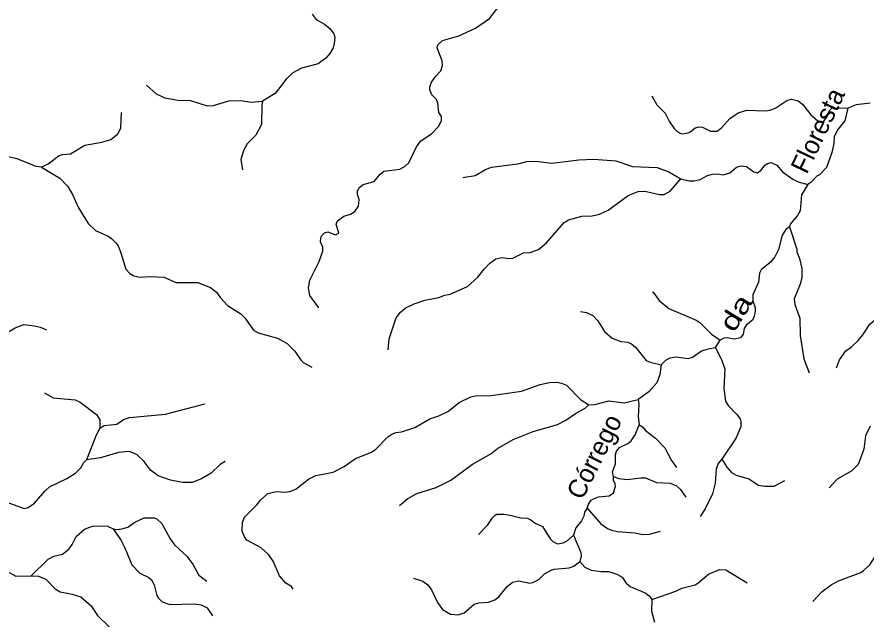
# Model space of a CAD drawing. Extents: x 577 to 602.9, y 7483.8 to 7511.6.
# Drawn here: x 589.273 to 592.922, y 7495.552 to 7498.138 of the extents above; entities that cross this region are included whole.
import ezdxf
from ezdxf.enums import TextEntityAlignment as Align

# ---------------------------------------------------------------- set-up
doc = ezdxf.new("R2010")
doc.units = 0
doc.header["$LTSCALE"] = 0.032
doc.layers.add('61', color=7, linetype='Continuous')
doc.layers.add('7', color=7, linetype='Continuous', lineweight=25)

msp = doc.modelspace()

# ---------------------------------------------------------------- linework, layer by layer
at = {"layer": '7'}
for points in [[(590.5706, 7496.8892), (590.5325, 7496.942), (590.5267, 7496.9755), (590.5325, 7497.0074), (590.5725, 7497.0883), (590.5872, 7497.1324), (590.5872, 7497.1488), (590.5782, 7497.1717), (590.579, 7497.1913), (590.5831, 7497.1995), (590.5954, 7497.2109), (590.6093, 7497.2158), (590.6428, 7497.2019), (590.6567, 7497.2101), (590.6453, 7497.2477), (590.651, 7497.2632), (590.678, 7497.282), (590.7066, 7497.2918), (590.7245, 7497.3033), (590.7409, 7497.3253), (590.7433, 7497.3548), (590.736, 7497.3768), (590.736, 7497.3907), (590.7442, 7497.4063), (590.7605, 7497.4193), (590.8079, 7497.4316), (590.8341, 7497.4635), (590.8496, 7497.4758), (590.9183, 7497.4847), (590.942, 7497.4978), (590.9575, 7497.5117), (590.9902, 7497.5804), (591.009, 7497.6057), (591.0548, 7497.636), (591.085, 7497.6678), (591.0973, 7497.6915), (591.0973, 7497.7112), (591.0858, 7497.7275), (591.0826, 7497.7676), (591.0768, 7497.7831), (591.0556, 7497.8035), (591.0474, 7497.8256), (591.0474, 7497.8387), (591.0548, 7497.8583), (591.0728, 7497.8845), (591.0948, 7497.9073), (591.1022, 7497.9294), (591.1006, 7497.9498), (591.0793, 7498.0054), (591.0826, 7498.0185), (591.1014, 7498.0373), (591.1717, 7498.0569), (591.2436, 7498.0896), (591.3041, 7498.1321), (591.3736, 7498.2229)], [(590.5414, 7498.1509), (590.5594, 7498.1272), (590.5946, 7498.1076), (590.6199, 7498.0872), (590.6346, 7498.0659), (590.6387, 7498.0512), (590.6371, 7498.025), (590.6314, 7498.0054), (590.6175, 7497.9809), (590.6011, 7497.9613), (590.5676, 7497.9376), (590.4965, 7497.918), (590.4589, 7497.8983), (590.4303, 7497.8714), (590.3829, 7497.8093), (590.3281, 7497.7766)], [(589.8297, 7497.8447), (589.8712, 7497.8076), (589.9088, 7497.7913), (589.9652, 7497.7815), (590.0183, 7497.7798), (590.0902, 7497.7561), (590.118, 7497.7578), (590.1842, 7497.7774), (590.2349, 7497.779), (590.2799, 7497.7725), (590.3281, 7497.7766)], [(592.0011, 7497.7998), (592.0234, 7497.7602), (592.0594, 7497.7251), (592.0757, 7497.6907), (592.097, 7497.6588), (592.1109, 7497.6458), (592.1297, 7497.6368), (592.1583, 7497.6409), (592.1697, 7497.6458), (592.1885, 7497.6621), (592.2041, 7497.6662), (592.2196, 7497.6654), (592.2531, 7497.6474), (592.2825, 7497.6474), (592.3013, 7497.6621), (592.3365, 7497.7022), (592.3724, 7497.7267), (592.41, 7497.7381), (592.4877, 7497.7357), (592.5098, 7497.7381), (592.5351, 7497.7479), (592.5817, 7497.779), (592.6021, 7497.7847), (592.6299, 7497.7774), (592.6487, 7497.7643), (592.6847, 7497.7185), (592.7135, 7497.693), (592.7223, 7497.6886), (592.7324, 7497.688), (592.7418, 7497.6924), (592.7525, 7497.7062), (592.7613, 7497.722), (592.7644, 7497.7346), (592.777, 7497.7478), (592.8441, 7497.7471)], [(590.3281, 7497.7766), (590.3248, 7497.7578), (590.324, 7497.676), (590.2995, 7497.6311), (590.2619, 7497.5935), (590.2488, 7497.5681), (590.2357, 7497.5264), (590.2418, 7497.482)], [(592.9405, 7497.7684), (592.88, 7497.761), (592.8441, 7497.7471)], [(589.3783, 7497.4929), (589.4077, 7497.5076), (589.4551, 7497.5428), (589.4698, 7497.5477), (589.5033, 7497.551), (589.5655, 7497.5869), (589.6374, 7497.6), (589.6766, 7497.6114), (589.7061, 7497.636), (589.72, 7497.6613), (589.7221, 7497.7279)], [(592.8441, 7497.7471), (592.8318, 7497.6915), (592.7999, 7497.6539), (592.7852, 7497.6229), (592.7836, 7497.5951), (592.7754, 7497.5559), (592.7517, 7497.4921), (592.7223, 7497.4602), (592.7125, 7497.4553), (592.6863, 7497.4283), (592.6716, 7497.4193)], [(589.3783, 7497.4929), (589.3562, 7497.4962), (589.2745, 7497.5289), (589.241, 7497.5354), (589.2074, 7497.533), (589.1412, 7497.5035), (589.0521, 7497.5125), (589.0309, 7497.5093), (589.0096, 7497.4937), (588.9916, 7497.4635), (588.9786, 7497.3752), (588.9671, 7497.3482), (588.9557, 7497.336), (588.9393, 7497.3286)], [(591.1893, 7497.4493), (591.242, 7497.4578), (591.2861, 7497.4831), (591.3123, 7497.4929), (591.4251, 7497.5068), (591.4643, 7497.5174), (591.5035, 7497.5191), (591.5722, 7497.5109), (591.6883, 7497.524), (591.7528, 7497.5272), (591.8468, 7497.5207), (591.918, 7497.4962), (592.0242, 7497.4913), (592.0741, 7497.4725), (592.1264, 7497.4431)], [(592.1264, 7497.4431), (592.1624, 7497.4349), (592.182, 7497.4341), (592.209, 7497.4398), (592.2408, 7497.4569), (592.2621, 7497.4635), (592.2833, 7497.4651), (592.3079, 7497.4602), (592.3365, 7497.4692), (592.3651, 7497.4937), (592.3855, 7497.4995), (592.4084, 7497.4962), (592.4403, 7497.4733), (592.4558, 7497.4684), (592.4722, 7497.4807), (592.4877, 7497.5011), (592.4991, 7497.5093), (592.5147, 7497.5125), (592.5384, 7497.5011), (592.5629, 7497.4733), (592.6079, 7497.4414), (592.6299, 7497.4308), (592.6716, 7497.4193)], [(589.3783, 7497.4929), (589.4576, 7497.4455), (589.4919, 7497.4095), (589.5123, 7497.376), (589.5377, 7497.318), (589.5785, 7497.2518), (589.6104, 7497.2215), (589.6644, 7497.197), (589.6791, 7497.1872), (589.6979, 7497.1676), (589.7077, 7497.1545), (589.7183, 7497.13), (589.7412, 7497.0548), (589.7576, 7497.0368), (589.7747, 7497.027), (589.8017, 7497.0213), (589.845, 7497.0237), (589.9063, 7497.0213), (589.9562, 7496.9984), (590.0502, 7496.9984), (590.105, 7496.9763), (590.1311, 7496.9567), (590.1483, 7496.9314), (590.1785, 7496.8995), (590.2349, 7496.8635), (590.2521, 7496.8455), (590.2897, 7496.7932), (590.3093, 7496.7818), (590.3935, 7496.7581), (590.4344, 7496.736), (590.4671, 7496.7033), (590.4916, 7496.6665), (590.5038, 7496.6543), (590.5399, 7496.6334)], [(590.8689, 7496.709), (590.8725, 7496.7556), (590.9027, 7496.8455), (590.9215, 7496.8709), (590.942, 7496.888), (590.9804, 7496.9068), (591.0254, 7496.9224), (591.0867, 7496.9338), (591.112, 7496.9436), (591.1349, 7496.9477), (591.2093, 7496.9812), (591.2542, 7497.0205), (591.2804, 7497.0556), (591.3049, 7497.0801), (591.3311, 7497.0989), (591.358, 7497.1055), (591.3866, 7497.1006), (591.4046, 7497.1022), (591.4496, 7497.1251), (591.4782, 7497.1267), (591.515, 7497.1398), (591.5485, 7497.1684), (591.6245, 7497.2551), (591.6433, 7497.2665), (591.7005, 7497.2828), (591.7455, 7497.2845), (591.7774, 7497.291), (591.8133, 7497.3082), (591.9, 7497.3719), (591.9433, 7497.3883), (591.9711, 7497.3899), (592.034, 7497.3752), (592.0553, 7497.376), (592.0798, 7497.3907), (592.1264, 7497.4431)], [(592.6716, 7497.4193), (592.6455, 7497.3736), (592.6389, 7497.3049), (592.6275, 7497.2853), (592.5964, 7497.2477), (592.594, 7497.2371)], [(592.594, 7497.2371), (592.5776, 7497.2256), (592.5613, 7497.2011), (592.5465, 7497.1398), (592.5302, 7497.1079), (592.5098, 7497.0842), (592.4713, 7497.0523), (592.464, 7497.0384), (592.4599, 7496.9992), (592.4354, 7496.9444), (592.4362, 7496.9191), (592.446, 7496.8905), (592.446, 7496.875), (592.4411, 7496.8513), (592.4337, 7496.8365), (592.4068, 7496.8145), (592.3986, 7496.8006), (592.3937, 7496.7752), (592.3822, 7496.7605), (592.3553, 7496.754), (592.3258, 7496.7605), (592.3111, 7496.7581), (592.2948, 7496.7499)], [(592.594, 7497.2371), (592.6242, 7497.1414), (592.625, 7497.1292), (592.6356, 7497.1014), (592.6463, 7497.0572), (592.6463, 7497.018), (592.6397, 7496.9902), (592.6128, 7496.9281), (592.6168, 7496.9036), (592.6381, 7496.8439), (592.6397, 7496.7695), (592.6553, 7496.6698), (592.6775, 7496.6092)], [(592.795, 7496.6314), (592.8081, 7496.6657), (592.8359, 7496.7041), (592.858, 7496.7196), (592.8882, 7496.7491), (592.9087, 7496.7728), (592.9381, 7496.8194), (592.9691, 7496.8439), (592.9871, 7496.8635), (592.9978, 7496.897), (593.0133, 7496.9853), (593.0215, 7497.0106), (593.0321, 7497.0294), (593.0566, 7497.0499), (593.0877, 7497.0613), (593.1155, 7497.063), (593.1359, 7497.0532)], [(592.0034, 7496.9576), (592.0079, 7496.9567), (592.0332, 7496.9207), (592.0749, 7496.8864), (592.1926, 7496.8357), (592.2073, 7496.8259), (592.258, 7496.7752), (592.2948, 7496.7499)], [(591.6944, 7496.8726), (591.721, 7496.8692), (591.7479, 7496.8562), (591.77, 7496.8325), (591.7986, 7496.7867), (591.8305, 7496.7589), (591.8681, 7496.7442), (591.8992, 7496.7409), (591.9147, 7496.7344), (591.931, 7496.7205), (591.9776, 7496.6632), (591.994, 7496.6559), (592.0422, 7496.6444)], [(589.0562, 7496.7401), (589.0758, 7496.7254), (589.0897, 7496.7205), (589.1143, 7496.7229), (589.1649, 7496.7442), (589.2655, 7496.803), (589.3023, 7496.8169), (589.348, 7496.812), (589.3734, 7496.8055), (589.4003, 7496.794)], [(592.0422, 7496.6444), (592.0618, 7496.6641), (592.0798, 7496.6739), (592.106, 7496.6788), (592.1583, 7496.6706), (592.1771, 7496.6763), (592.2155, 7496.7049), (592.2457, 7496.7123), (592.2752, 7496.7188), (592.2948, 7496.7499)], [(592.2752, 7496.7188), (592.303, 7496.6632), (592.3152, 7496.6273), (592.3111, 7496.5423), (592.3177, 7496.4883), (592.3291, 7496.4695), (592.3667, 7496.4311), (592.3814, 7496.4115), (592.3847, 7496.4), (592.3839, 7496.3788), (592.3643, 7496.3306), (592.303, 7496.2382)], [(592.0422, 7496.6444), (592.0365, 7496.6028), (592.0234, 7496.5668), (591.9883, 7496.5284), (591.9433, 7496.4949)], [(590.4599, 7495.6804), (590.4523, 7495.6914), (590.4286, 7495.7069), (590.4017, 7495.7379), (590.3739, 7495.8009), (590.3551, 7495.8279), (590.3224, 7495.8581), (590.2611, 7495.8908), (590.2504, 7495.9055), (590.2406, 7495.93), (590.2423, 7495.9676), (590.2513, 7495.9897), (590.3044, 7496.0428), (590.3207, 7496.0649), (590.3518, 7496.0919), (590.387, 7496.1001), (590.4237, 7496.0976), (590.4458, 7496.1001), (590.472, 7496.1099), (590.5259, 7496.1524), (590.557, 7496.1687), (590.6322, 7496.1834), (590.6788, 7496.208), (590.7278, 7496.2423), (590.7965, 7496.2684), (590.8153, 7496.2815), (590.8676, 7496.3355), (590.8848, 7496.3469), (590.9027, 7496.3535), (590.9264, 7496.3559), (590.9828, 7496.3747), (591.0474, 7496.4123), (591.0867, 7496.4254), (591.1243, 7496.4434), (591.1733, 7496.4826), (591.2232, 7496.5071), (591.242, 7496.5112), (591.3114, 7496.512), (591.4414, 7496.5316), (591.5223, 7496.5594), (591.5616, 7496.5676), (591.5934, 7496.5692), (591.6131, 7496.566), (591.6351, 7496.5562), (591.6956, 7496.4957), (591.7308, 7496.4728)], [(589.3919, 7496.5239), (589.429, 7496.5022), (589.5238, 7496.4932), (589.545, 7496.4834), (589.6153, 7496.4303), (589.6292, 7496.4074), (589.6292, 7496.3723)], [(589.6292, 7496.3723), (589.6472, 7496.3829), (589.7028, 7496.3894), (589.7314, 7496.409), (589.7567, 7496.4172), (589.912, 7496.4319), (590.0812, 7496.4763)], [(591.7308, 7496.4728), (591.7569, 7496.4744), (591.8174, 7496.4891), (591.8828, 7496.481), (591.9433, 7496.4949)], [(591.9433, 7496.4949), (591.9458, 7496.4736), (591.9425, 7496.4221), (591.9466, 7496.387)], [(590.9167, 7496.0397), (590.9534, 7496.0706), (590.991, 7496.0911), (591.0752, 7496.1172), (591.1373, 7496.1491), (591.2313, 7496.2178), (591.309, 7496.2619), (591.3384, 7496.284), (591.4054, 7496.324), (591.4913, 7496.3584), (591.5959, 7496.3878), (591.6319, 7496.4058), (591.6736, 7496.4352), (591.7152, 7496.4581), (591.7308, 7496.4728)], [(589.6292, 7496.3723), (589.6129, 7496.342), (589.572, 7496.2357)], [(591.8362, 7496.1646), (591.8329, 7496.1842), (591.846, 7496.2194), (591.8452, 7496.2578), (591.8493, 7496.2733), (591.8624, 7496.2897), (591.9008, 7496.3069), (591.9131, 7496.3175), (591.9294, 7496.3436), (591.9466, 7496.387)], [(591.9466, 7496.387), (591.9621, 7496.3772), (591.9744, 7496.3616), (592.0177, 7496.3297), (592.0577, 7496.2881), (592.0855, 7496.2333), (592.1074, 7496.2036)], [(592.9405, 7496.3812), (592.9201, 7496.3396), (592.9127, 7496.2823), (592.889, 7496.2153), (592.8612, 7496.1883), (592.7975, 7496.1524), (592.7642, 7496.1159)], [(590.1678, 7496.2288), (590.1466, 7496.2161), (590.1082, 7496.1785), (590.0665, 7496.1548), (590.0257, 7496.1393), (589.9848, 7496.1393), (589.9333, 7496.1491), (589.8802, 7496.1671), (589.8475, 7496.1916), (589.8205, 7496.2284), (589.7886, 7496.2586), (589.7559, 7496.2717), (589.7093, 7496.2668), (589.6317, 7496.2447), (589.572, 7496.2357)], [(588.8599, 7495.8632), (588.8944, 7495.8794), (588.9401, 7495.9088), (588.9949, 7495.9333), (589.0317, 7495.9546), (589.0619, 7495.9676), (589.0889, 7495.9701), (589.1069, 7495.9774), (589.1322, 7495.9954), (589.169, 7496.0347), (589.1984, 7496.0518), (589.2132, 7496.0559), (589.2295, 7496.0543), (589.3047, 7496.0273), (589.3211, 7496.0314), (589.348, 7496.0494), (589.3922, 7496.1017), (589.4126, 7496.1205), (589.4878, 7496.1556), (589.5246, 7496.1785), (589.5475, 7496.2022), (589.5606, 7496.2243), (589.572, 7496.2357)], [(592.303, 7496.2382), (592.2874, 7496.2202), (592.2784, 7496.1957), (592.2743, 7496.136), (592.2621, 7496.0894), (592.231, 7496.0257), (592.2097, 7495.9931)], [(592.303, 7496.2382), (592.3234, 7496.2039), (592.3438, 7496.1818), (592.3634, 7496.1704), (592.419, 7496.154), (592.4607, 7496.127), (592.4877, 7496.1229), (592.5277, 7496.1229), (592.5727, 7496.1468)], [(591.7242, 7496.0281), (591.73, 7496.0461), (591.7414, 7496.0625), (591.7504, 7496.069), (591.7725, 7496.0772), (591.8182, 7496.0813), (591.8362, 7496.0943), (591.8452, 7496.1221), (591.8444, 7496.1328), (591.8362, 7496.1483), (591.8362, 7496.1646)], [(591.8362, 7496.1646), (591.8591, 7496.1565), (591.8951, 7496.1516), (591.9547, 7496.1589), (591.9744, 7496.1581), (592.0218, 7496.1385), (592.0798, 7496.136), (592.1076, 7496.1238), (592.1231, 7496.1107), (592.1471, 7496.076)], [(592.6933, 7495.6271), (592.7337, 7495.6701), (592.7722, 7495.6995), (592.804, 7495.7159), (592.8997, 7495.7518), (592.9119, 7495.76), (592.9381, 7495.7854), (592.9749, 7495.8409), (593.0043, 7495.8695), (593.0427, 7495.8908), (593.077, 7495.9047), (593.1433, 7495.9194), (593.18, 7495.9431), (593.1997, 7495.9693), (593.2225, 7496.0494), (593.2446, 7496.0788), (593.2691, 7496.0886), (593.292, 7496.0902), (593.3509, 7496.0682)], [(591.2568, 7495.9152), (591.2967, 7495.9562), (591.3163, 7495.9873), (591.3278, 7495.9987), (591.3351, 7496.002), (591.3654, 7496.002), (591.3932, 7495.9987), (591.4381, 7495.9864), (591.4676, 7495.9848), (591.4823, 7495.9783), (591.5003, 7495.9644), (591.5313, 7495.9497), (591.5648, 7495.8965), (591.5763, 7495.8851), (591.5959, 7495.8753), (591.6212, 7495.8794), (591.6376, 7495.8883), (591.6654, 7495.9129)], [(591.7242, 7496.0281), (591.712, 7496.011), (591.7095, 7495.9946), (591.6989, 7495.9734), (591.6744, 7495.9439), (591.6654, 7495.9129)], [(591.7242, 7496.0281), (591.7831, 7495.9611), (591.8109, 7495.9415), (591.828, 7495.9341), (591.8534, 7495.9276), (591.9286, 7495.9219), (591.9629, 7495.9153), (591.9923, 7495.917), (592.0393, 7495.9301)], [(589.6864, 7495.9398), (589.7003, 7495.9374), (589.7232, 7495.939), (589.7494, 7495.9472), (589.7796, 7495.9685), (589.8205, 7495.9873), (589.8622, 7495.9864), (589.8753, 7495.9815), (589.8957, 7495.9627), (589.9317, 7495.8965), (589.9496, 7495.8712), (590.0044, 7495.8205), (590.0306, 7495.7845), (590.0551, 7495.7412), (590.0896, 7495.7151)], [(589.3341, 7495.7371), (589.4069, 7495.8091), (589.4322, 7495.8221), (589.4682, 7495.8303), (589.496, 7495.8516), (589.5107, 7495.872), (589.5279, 7495.9063), (589.563, 7495.9382), (589.5973, 7495.9505), (589.6153, 7495.9529), (589.6619, 7495.9505), (589.6864, 7495.9398)], [(589.6864, 7495.9398), (589.7208, 7495.89), (589.7371, 7495.8581), (589.7665, 7495.7854), (589.8009, 7495.7486), (589.8393, 7495.7306), (589.8516, 7495.7208), (589.863, 7495.6987), (589.8744, 7495.6538), (589.8818, 7495.6423), (589.8973, 7495.626), (589.93, 7495.6145), (590.0379, 7495.617), (590.0641, 7495.6129), (590.0911, 7495.5998), (590.1137, 7495.5653)], [(591.6654, 7495.9129), (591.6964, 7495.8377), (591.6973, 7495.823), (591.6924, 7495.7992)], [(588.9622, 7495.814), (588.9835, 7495.814), (589.0497, 7495.8189), (589.0905, 7495.8123), (589.1249, 7495.7927), (589.1494, 7495.7682), (589.1796, 7495.7592), (589.2262, 7495.7592), (589.2679, 7495.7363), (589.3341, 7495.7371)], [(590.9773, 7495.7276), (591.0172, 7495.7151), (591.0384, 7495.6995), (591.054, 7495.6775), (591.0809, 7495.6235), (591.1022, 7495.5933), (591.1365, 7495.5728), (591.17, 7495.5704), (591.1954, 7495.5794), (591.2387, 7495.6161), (591.2583, 7495.6219), (591.2992, 7495.6251), (591.327, 7495.6341), (591.3441, 7495.648), (591.3793, 7495.6922), (591.403, 7495.7102), (591.43, 7495.7159), (591.4766, 7495.7061), (591.4905, 7495.7093), (591.5158, 7495.7216), (591.5403, 7495.7461), (591.5697, 7495.7616), (591.582, 7495.7657), (591.6466, 7495.7715), (591.6662, 7495.7796), (591.6924, 7495.7992)], [(591.6924, 7495.7992), (591.7144, 7495.7747), (591.7414, 7495.7616), (591.7839, 7495.7559), (591.8166, 7495.7559), (591.8509, 7495.7453), (591.8738, 7495.7322), (591.8918, 7495.7069), (591.909, 7495.6914), (591.976, 7495.6636), (591.9923, 7495.6505), (592.0022, 7495.6366)], [(592.0022, 7495.6366), (592.1043, 7495.6717), (592.1305, 7495.6848), (592.1877, 7495.6995), (592.2, 7495.7061), (592.2457, 7495.7445), (592.2923, 7495.7649), (592.3201, 7495.7641), (592.4107, 7495.7074)], [(589.3341, 7495.7371), (589.3652, 7495.7363), (589.3971, 7495.7232), (589.4371, 7495.6824), (589.4584, 7495.6685), (589.5099, 7495.6587), (589.5475, 7495.6472), (589.5924, 7495.6096), (589.6194, 7495.5671), (589.6701, 7495.5181), (589.6815, 7495.5099), (589.7175, 7495.5001), (589.7395, 7495.4997)], [(592.0022, 7495.6366), (591.9997, 7495.5867), (592.0128, 7495.5393)]]:
    msp.add_lwpolyline(points, dxfattribs=at)

# ---------------------------------------------------------------- texts
at = {"layer": '61'}
for s, rotation, p in [('Floresta', 64.456, (592.7507, 7497.6336)), ('Córrego', 63.393, (591.7895, 7496.2322))]:
    msp.add_text(s, height=0.08, rotation=rotation, dxfattribs=at).set_placement(p, align=Align.CENTER)
at = {"layer": '61', "width": 1.35}
msp.add_text('da', height=0.08, rotation=58.562, dxfattribs=at).set_placement((592.3966, 7496.8472), align=Align.CENTER)

doc.saveas('drawing.dxf')
